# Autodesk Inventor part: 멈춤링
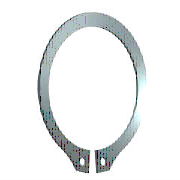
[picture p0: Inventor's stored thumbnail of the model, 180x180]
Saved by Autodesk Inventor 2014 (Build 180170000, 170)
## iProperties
IsCustomPart: 0
Created: 2009-02
Part Number: 멈춤링
Material: 강, 연강
Description: 리테이닝 링(C형)
Document SubType Name: Modeling
Standard: KS B 1336
Designer: KYOUNG IL JANG
Standards Organization: KS
Language: ko-KR
Size Designation: 22 x 1.2
Categories: <MemberInstance><Categories><Category DisplayName="샤프트 부품" InternalName="7f7aeb1f-a693-4053-b835-cee3144e0d98" Mnemonic="SHFT"><Category DisplayName="써클립" Inter
Density: 7.86 g/cm^3
Appearance: 강철
Mass: 1.8286 g
Surface Area: 5.91219 cm^2
Volume: 0.232646 cm^3
Author: KYOUNG IL JANG
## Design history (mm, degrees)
sketch "스케치1"
  geometry: L1 (-6, 0)-(6, 0) reference; L2 (0, 20.189)-(0, -80.536) reference; L3 (-48.09, 0)-(48.09, 0) reference; L4 (-0.5, -21.488)-(-0.5, -25.588); L5 (-0.5, -6.54)-(-0.5, -13.29); L6 (-2.795, 2.7)-(3.672, 2.7); L7 (0.5, -6.54)-(0.5, -13.29); L8 (0.5, -21.488)-(0.5, -25.588); C1 r 1 at (-2, -23.437); C2 r 1 at (2, -23.437); A1 r 10.5 centre (0, -11) between (0.5, -21.488) and (-0.5, -21.488); A2 r 13.025 centre (0, -10.325) between (5.149, -22.289) and (-5.149, -22.289); A3 r 14.597 centre (0, -11) between (-2.318, -25.411) and (-0.5, -25.588); A4 r 2 centre (-2, -23.437) between (-3.97, -23.781) and (-2.318, -25.411); A5 r 2 centre (-5.94, -24.126) between (-3.97, -23.781) and (-5.149, -22.289); A6 r 2 centre (5.94, -24.126) between (5.149, -22.289) and (3.97, -23.781); A7 r 2 centre (2, -23.437) between (2.318, -25.411) and (3.97, -23.781); A8 r 14.597 centre (0, -11) between (0.5, -25.588) and (2.318, -25.411)
  constraints: 16 point on circle, 12 end point, 10 centre point, 9 symmetric about line, 5 point on line, 4 tangent, 3 coincident, 2 horizontal, 1 perpendicular, 1 vertical, 5 other
  dimensions: "d0" = 21 diameter of A1 (= ND); "d1" = 4.1 distance of L4.end L4.start (= SRB2); "d6" = 0.5 distance between parallel lines of L2 L5 (= 0.25 x SD5); "d7" = 2.7 distance between parallel lines of L6 L3 (= SRB1); "d8" = 0.675 distance of A1.centre A2.centre (= 0.25 x SRB1); "d9" = 2 radius of A4 (= SD5); "d10" = 2 radius of A5 (= SD5); "d11" = 1.5 distance from line of L4 A4.centre (= 0.75 x SD5); "d12" = 2 diameter of C1 (= SD5); "d13" = 2 diameter of C2 (= SD5); "d14" = 11 distance from line of A1.centre L1 (= 0.5 x WD)
extrude "본체" new body sketch "스케치1" distance "d2" = 1.2 (= SD); taper "d3" = 0 deg
workaxis "Work Axis1"
workplane "Work Plane1"
body "Solid1"
other parameters: "WD" = 22 (= WDMIN) [user parameter; used in 1 equation term], "SD" = 1.2 [user parameter; used in 1 equation term], "SRB1" = 2.7 [user parameter; used in 2 equation terms], "ND" = 21 [user parameter; used in 1 equation term], "SRB2" = 4.1 [user parameter; used in 1 equation term], "SD5" = 2 [user parameter; used in 6 equation terms], "d15" = 0, "d16" = 0, "d17" = 0, "d41" = 0, "d42" = 0, "WDMIN" = 22 [user parameter; used in 1 equation term], "SD3" = 20.5 [user parameter], "WDMAX" = 24 [user parameter]
